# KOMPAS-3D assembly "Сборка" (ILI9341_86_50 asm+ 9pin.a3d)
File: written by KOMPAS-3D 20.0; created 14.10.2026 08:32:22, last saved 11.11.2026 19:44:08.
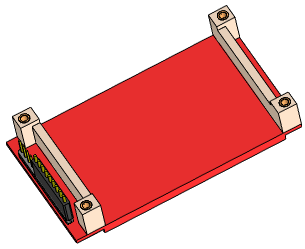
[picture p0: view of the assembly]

Document properties: Полное имя файла: D:\myProjects\Progect_esp32\box_compas\монитор\ILI9341_86_50 asm+ 9pin.a3d

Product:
- Part/product: Сборка
    Масса: 0.111547
  - Component [assembly]: Сборка  | qty 2  | Масса: 0.0139528; source file: ..\корпус\п-стойка_1 asm.a3d
  - Component [detail]: Деталь  | Масса: 0.00180884; source file: ..\разъемы\pls_14.m3d
  - Component [detail]: Деталь  | Масса: 0.0790697; source file: ILI9341_86_50.m3d
  - Component [detail]: Деталь  | Масса: 0.00276261; source file: ..\разъемы\pbs_9.m3d

Referenced files in D:\myProjects\Progect_esp32\box_compas\монитор\: ILI9341_86_50.m3d
Referenced files in D:\myProjects\Progect_esp32\box_compas\разъемы\: pls_14.m3d, pbs_9.m3d
Referenced files in D:\myProjects\Progect_esp32\box_compas\корпус\: п-стойка_1 asm.a3d
Referenced files in D:\RicWork\Project-EPS32\box_compas\корпус\: п-стойка_1 asm.a3d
